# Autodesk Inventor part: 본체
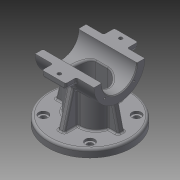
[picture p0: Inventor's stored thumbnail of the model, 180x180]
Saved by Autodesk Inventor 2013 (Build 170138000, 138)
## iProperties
Created: 2015-12
Part Number: 본체
Material: 일반
Document SubType Name: Modeling
Designer: mduedu
Density: 2.71 g/cm^3
Author: mduedu
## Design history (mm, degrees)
sketch "스케치1"
  geometry: L1 (40, 35)-(-40, 35); L2 (-40, 35)-(-40, -35); L3 (-40, -35)-(40, -35); L4 (40, -35)-(40, 35); L5 (40, 35)-(-40, -35); L6 (-40, 35)-(40, -35); 2 further points
  constraints: 12 end point, 2 midpoint, 2 parallel, 1 coincident, 1 horizontal, 1 perpendicular, 3 other
  dimensions: "d0" = 80 distance of L2.end L3.end; "d2" = 70 distance of L1.end L2.end
extrude "돌출1" new body sketch "스케치1" distance "d3" = 10; taper "d4" = 0 deg
sketch "스케치2"
  geometry: C1 r 32.5 at (75, 0); 1 further point
  constraints: 1 centre point
  dimensions: "d5" = 65 diameter of C1; "d116" = 75 distance of point (0, 0) C1.centre
extrude "돌출2" join sketch "스케치2" stored distance "d7" = 75; taper "d8" = 0 deg
sketch "스케치3"
  geometry: L1 (-27.5, -20)-(27.5, -20); L2 (27.5, -20)-(27.5, 20); L3 (27.5, 20)-(-27.5, 20); L4 (-27.5, 20)-(-27.5, -20); L5 (-27.5, -20)-(27.5, 20); L6 (27.5, -20)-(-27.5, 20); 1 further point
  constraints: 12 end point, 2 midpoint, 2 parallel, 1 horizontal, 1 perpendicular
  dimensions: "d9" = 55 distance of L2.end L3.end; "d11" = 40 distance of L1.end L2.end
extrude "돌출3" new body sketch "스케치3" stored distance "d12" = 75; taper "d13" = 0 deg
fillet "모깎기1"
fillet "모깎기2"
feature "결합1"
  node "솔리드2"
sketch "스케치4"
  geometry: L1 (-37.5, 42.5)-(37.5, 42.5) reference; L2 (32.5, 42.5)-(40.151, 10); L3 (37.5, 42.5)-(37.5, 107.5) reference; L4 (53.151, 0)-(53.151, 10) reference; L5 (53.151, 10)-(-53.151, 10) reference; 1 further point
  constraints: 2 end point, 2 point on line
  dimensions: "d15" = 5 distance from line of L2.start L3; "d117" = 13 distance from line of L2.end L4
sketch "스케치5"
  geometry: L1 (10, 37.151)-(54.507, 25.225); L2 (0, 53.151)-(10, 53.151) reference; L3 (10, -53.151)-(10, 53.151) reference; 2 further points
  constraints: 2 end point, 1 point on line, 2 other
  dimensions: "d118" = 16 distance from line of L1.start L2; "d119" = 75 deg angle of L1 L3
feature "리브1" dims "d19" = 1, "d20" = 8, "d21" = 0, "d22" = 0, "d23" = 1, "d24" = 1
feature "리브2" dims "d25" = 1, "d26" = 8, "d27" = 0, "d28" = 0, "d29" = 1, "d30" = 1
fillet "모깎기4" dims "d31" = 2
fillet "모깎기5" dims "d32" = 2
fillet "모깎기6" dims "d33" = 2
sketch "스케치6"
  geometry: L1 (0, 0)-(-29.698, 29.698); L2 (0, 0)-(-42, 0); A1 r 42 centre (0, 0) between (-29.698, 29.698) and (-42, 0); 5 further points
  constraints: 4 end point, 2 coincident, 2 point on circle, 1 centre point, 1 horizontal, 5 other
  dimensions: "d122" = 45 deg angle of L1 L2; "d126" = 360 deg dimension on point (0, 0) point (-29.698, 29.698) (derived); "d150" = 84 diameter of A1
hole "구멍1" sketch "스케치6" at (-29.698, 29.698), (-29.698, -29.698), (29.698, -29.698), (29.698, 29.698) diameter "d34" = 7; stored, may be unused: countersink angle "d38" = 90 deg, drill point angle "d40" = 118 deg; dims "d35" = 6, "d36" = 12, "d37" = 3, "d39" = 8
fillet "모깎기13" dims "d131" = 3
hole "구멍2" diameter "d44" = 45; stored, may be unused: countersink angle "d48" = 90 deg, drill point angle "d50" = 118 deg; dims "d42" = 10, "d43" = 10, "d45" = 6, "d46" = 4, "d47" = 2, "d49" = 8
sketch "스케치7" dims "d52" = 26.5
  geometry: L1 (0, 0)-(32.5, 0); L2 (0, 0)-(22.981, 22.981); A1 r 32.5 centre (0, 0) between (32.5, 0) and (22.981, 22.981) reference; 3 further points
  constraints: 4 end point, 2 point on circle, 1 coincident, 1 horizontal, 1 point on line, 3 other
  dimensions: "d51" = 45 deg angle of L2 L1
hole "구멍3" sketch "스케치7" at (18.738, 18.738) diameter "d54" = 2.459; stored, may be unused: countersink angle "d58" = 90 deg, drill point angle "d60" = 118 deg; dims "d55" = 8, "d56" = 4, "d57" = 2, "d59" = 10
sketch "스케치8"
  geometry: L1 (67.5, 31.623)-(67.5, 46); L2 (67.5, 46)-(82.5, 46); L3 (82.5, 46)-(82.5, 31.623); A1 r 32.5 centre (75, 0) between (82.5, 31.623) and (67.5, 31.623) reference; 2 further points
  constraints: 6 end point, 2 point on circle, 1 horizontal, 1 midpoint, 1 parallel, 1 vertical, 1 vertical alignment
  dimensions: "d64" = 15 distance of L1.end L2.end; "d66" = 46 distance from line of L2 A1.centre
extrude "돌출4" join sketch "스케치8" stored distance "d67" = 30; taper "d68" = 0 deg
fillet "모깎기8" dims "d69" = 3
fillet "모깎기9" dims "d70" = 2
node "작업 평면2"
sketch "스케치16"
  geometry: L1 (33.166, 67.5)-(44, 67.5) reference; L2 (42.5, 67.5)-(28.53, 59.434); L3 (46, 70.5)-(46, 79.5) reference; 2 further points
  constraints: 2 end point, 1 point on line, 2 other
  dimensions: "d138" = 30 deg angle of L2 L1; "d139" = 3.5 distance from line of L2.start L3
feature "리브3" sketch "스케치16" dims "d140" = 1, "d141" = 3, "d142" = 0, "d143" = 0, "d144" = 1, "d145" = 1
fillet "모깎기14" dims "d146" = 1
fillet "모깎기15" dims "d147" = 1
sketch "스케치9"
  geometry: L1 (-76, 82.5)-(76, 82.5); L2 (76, 82.5)-(76, 0); L3 (76, 0)-(-76, 0); L4 (-76, 0)-(-76, 82.5); L5 (-46, 4.5)-(-46, -4.5) reference; C1 r 32.5 at (0, 0) reference; 2 further points
  constraints: 8 end point, 2 parallel, 1 coincident, 1 horizontal, 1 midpoint, 1 perpendicular
  dimensions: "d71" = 50 distance edge to line of C1 L1; "d72" = 30 distance between parallel lines of L4 L5
extrude "돌출5" cut sketch "스케치9" stored distance "d73" = 0; taper "d74" = 0 deg
node "작업 평면1"
sketch "스케치10"
  geometry: L1 (-7.5, 15)-(7.5, 15); L2 (-7.5, -15)-(7.5, -15); A1 r 20 centre (-7.5, 0) between (-7.5, 20) and (-26.742, 5.455) reference; A2 r 20 centre (7.5, 0) between (26.742, 5.455) and (7.5, 20) reference; A3 r 15 centre (-7.5, 0) between (-7.5, 15) and (-7.5, -15); A4 r 15 centre (7.5, 0) between (7.5, -15) and (7.5, 15); 1 further point
  constraints: 7 point on circle, 4 end point, 4 tangent, 3 point on line, 2 centre point, 2 coincident, 1 horizontal
  dimensions: "d77" = 5 radial gap between concentric circles of A3 A1
extrude "돌출6" cut sketch "스케치10" stored distance "d78" = 50; taper "d79" = 0 deg
fillet "모깎기10" dims "d80" = 3
sketch "스케치11"
  geometry: 2 further points
  constraints: 1 coincident
hole "구멍4" sketch "스케치11" at (0, 0) diameter "d81" = 12; stored, may be unused: countersink angle "d85" = 90 deg, drill point angle "d87" = 118 deg; dims "d82" = 8, "d83" = 40, "d84" = 10, "d86" = 10
sketch "스케치12"
  geometry: C1 r 10 at (0, 0); 1 further point
  constraints: 1 centre point, 1 coincident
  dimensions: "d88" = 20 diameter of C1
extrude "돌출7" cut sketch "스케치12" distance "d89" = 5; taper "d90" = 0 deg
chamfer "모따기1" distance "d91" = 1; stored, may be unused: second distance "d92" = 2, angle "d93" = 45 deg
fillet "모깎기11" dims "d94" = 0.5
sketch "스케치13"
  geometry: L1 (-3, 10.834)-(-3, 1.039) reference; L2 (27, 1.039)-(27, 10.834) reference; L3 (-3, 5.936)-(27, 5.936); L4 (24, 12.834)-(0, 12.834) reference; L5 (12, 12.834)-(12, -33.166); 1 further point
  constraints: 4 end point, 4 midpoint, 1 perpendicular, 1 point on line
hole "구멍5" sketch "스케치13" at (12, 5.936) diameter "d101" = 4.5; stored, may be unused: countersink angle "d105" = 90 deg, drill point angle "d107" = 0 deg; dims "d102" = 6, "d103" = 4, "d104" = 2, "d106" = 8
fillet "모깎기12" dims "d115" = 0.3
fillet "모깎기16" dims "d155" = 0.5
chamfer "모따기2" distance "d157" = 1; stored, may be unused: second distance "d158" = 2, angle "d159" = 45 deg
node "솔리드1"
mirror "대칭1"
mirror "대칭2"
pattern_circular "원형 패턴1" dims angle "d62" = 360 deg
mirror "대칭3"
mirror "대칭7"
mirror "대칭4"
mirror "대칭6"
other parameters: "d137" = -5
